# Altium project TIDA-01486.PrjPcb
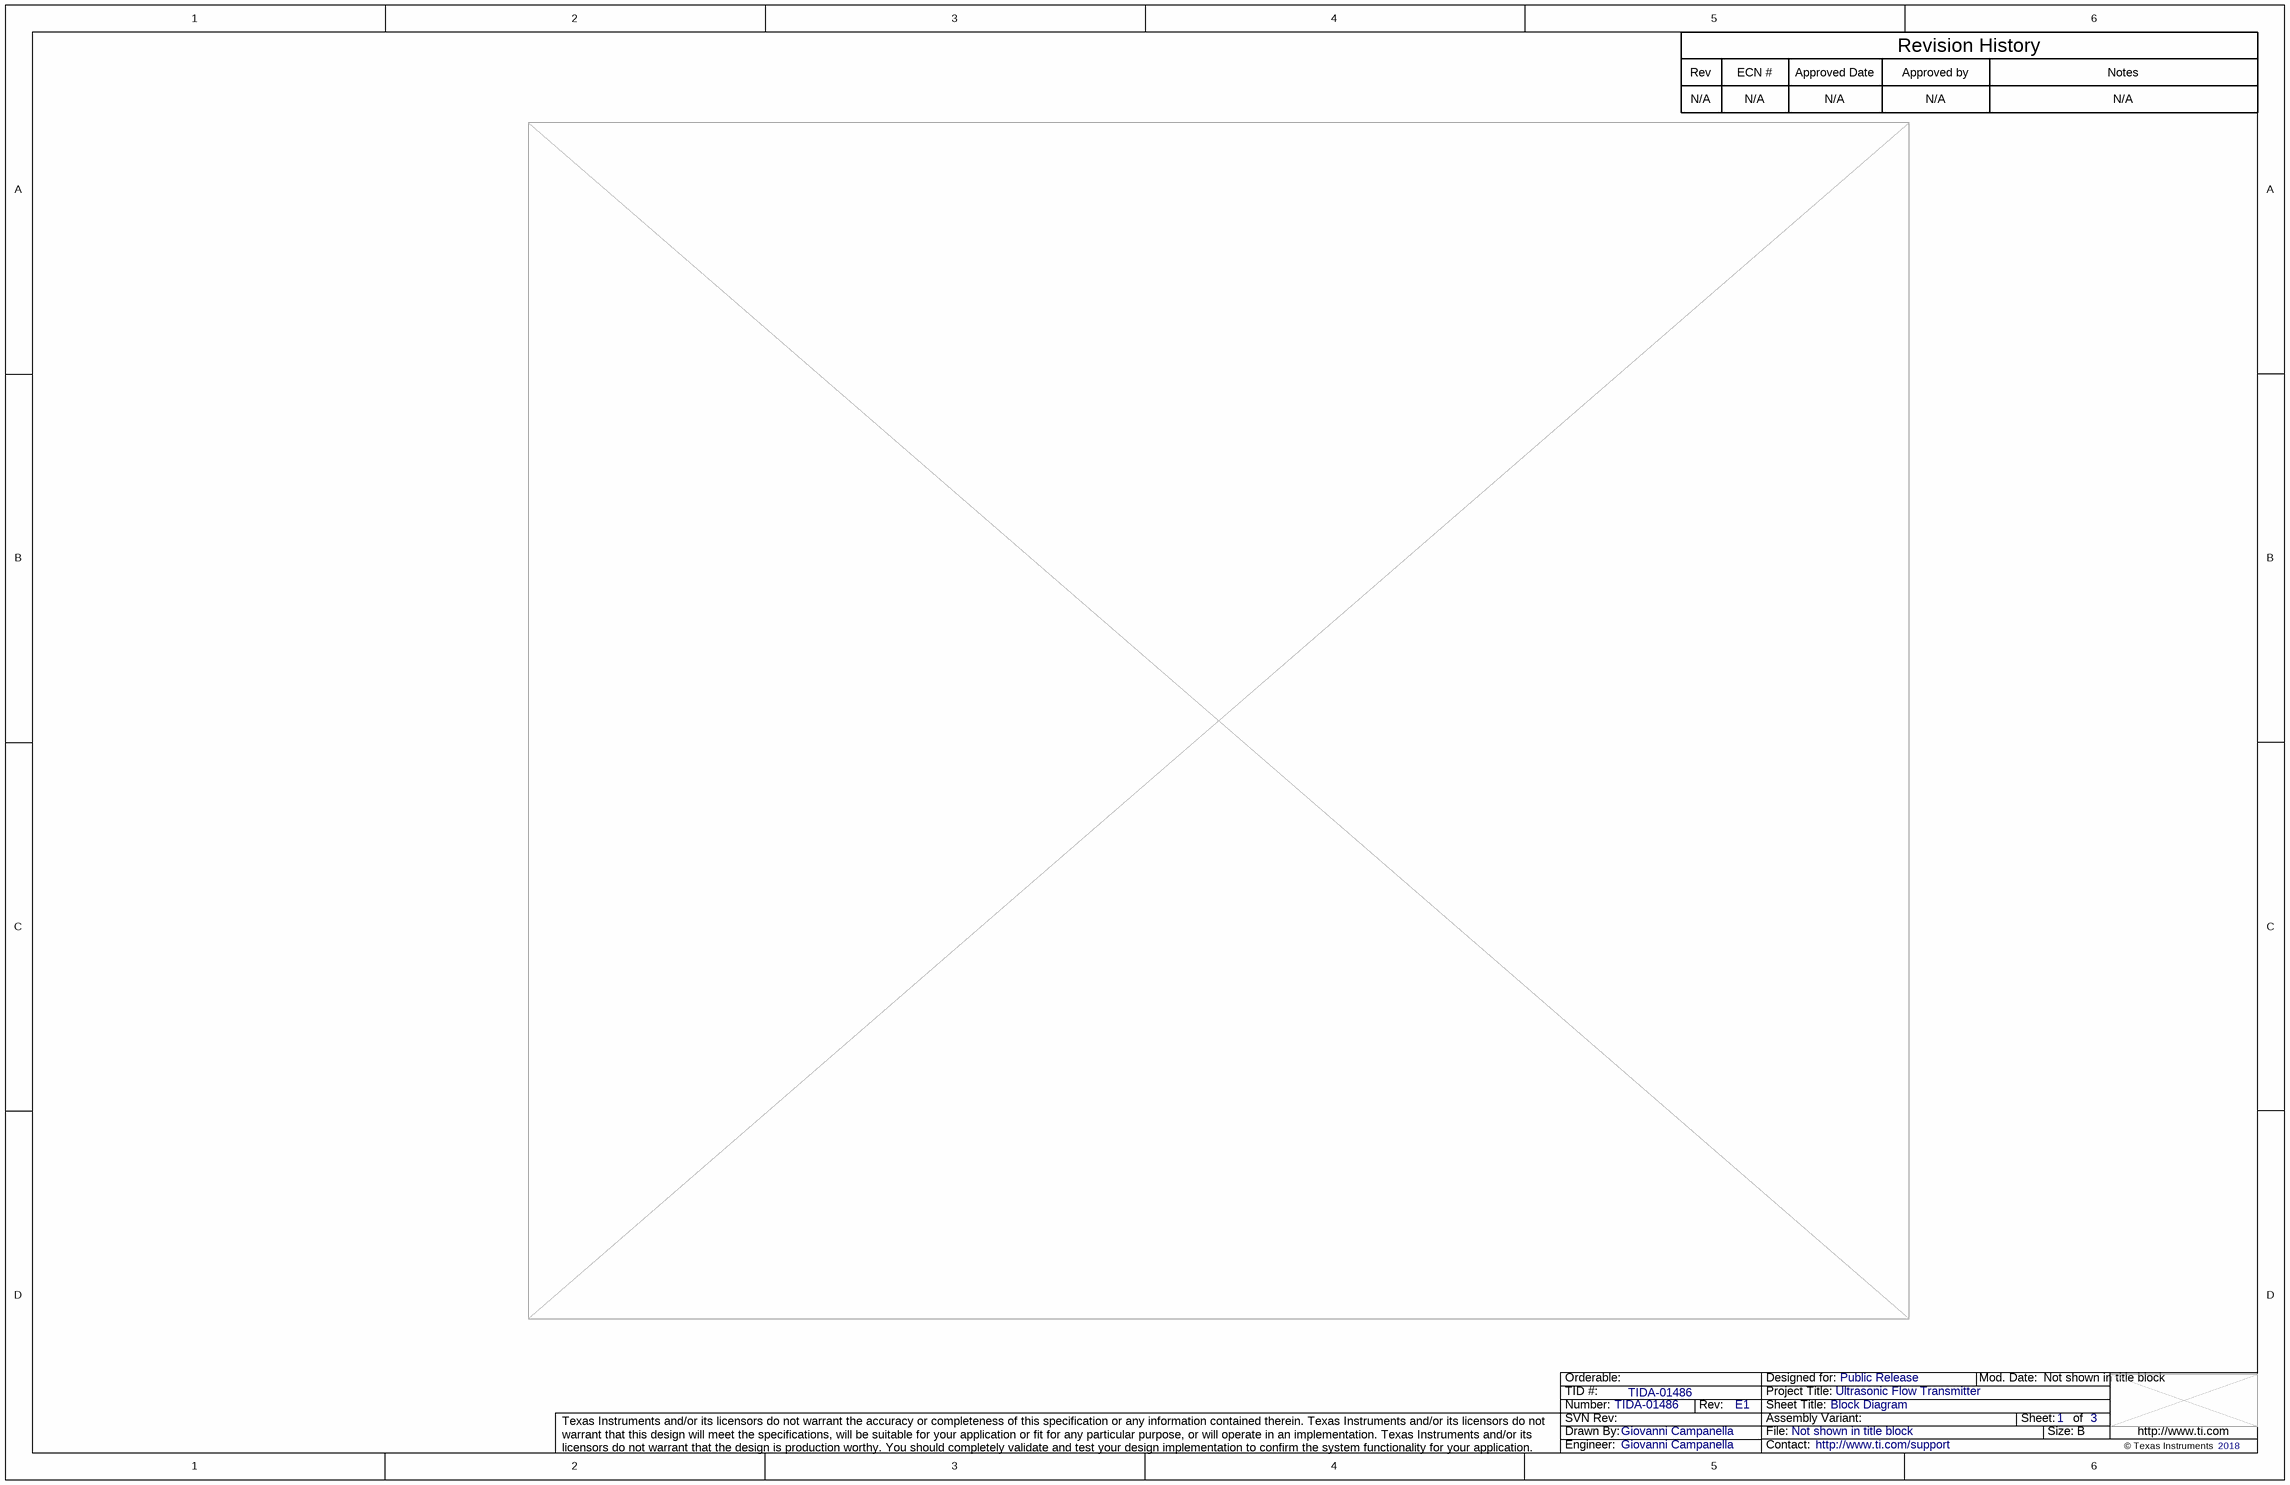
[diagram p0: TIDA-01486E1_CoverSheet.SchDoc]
TID: TIDA-01486; TechSupport: http://www.ti.com/support; SCH_Rev: E1; PRJ_Title: Ultrasonic Flow Transmitter; PRJ_Number: TIDA-01486; PRJ_Engineer: Giovanni Campanella; PRJ_Customer: Public Release; PCB_Rev: E1; PCB_Layout: Giovanni Campanella; CopyrightYear: 2018
3 sheets, 141 parts. Net scope: global (net labels, ports and power ports of the same name join across sheets).
Board file: TIDA-01486E1_PCB.PcbDoc
Sheets:
  TIDA-01486E1_CoverSheet.SchDoc
  TIDA-01486E1_Schematic.SchDoc
  TIDA-01486E1_Hardware.SchDoc

## Sheet TIDA-01486E1_CoverSheet.SchDoc: Block Diagram
size 431 x 279 mm; Date: Not shown in title block; ApprovedBy: Not shown in title block; CheckedBy: Not shown in title block; Author: Not shown in title block; CompanyName: Not shown in title block; DrawnBy: Giovanni Campanella; Engineer: Giovanni Campanella; Organization: Not shown in title block; Address1: Not shown in title block; Address2: Not shown in title block; Address3: Not shown in title block; Address4: Not shown in title block; DocumentNumber: 1; Revision: Use project parameter SCH_Rev; SheetNumber: 1; SheetTotal: 3; PageSetup: Record=PageOptions¦CenterHorizontal=True¦CenterVertical=True¦PrintScale=1.00¦XCorrection=1.00¦YCorrection=1.00¦PrintKind=0¦BorderSize=5000000¦LeftOffset=0¦BottomOffset=0¦Orientation=2¦PaperLength=1000¦PaperWidth=1000¦Scale=100¦PaperSource=15¦PrintQuality=600¦MediaType=1¦DitherType=10¦PaperKind=Letter¦PrintScaleMode=1

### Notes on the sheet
- Rev
- N/A
- ECN #
- Approved Date
- Approved by
- Revision History
- Notes

## Sheet TIDA-01486E1_Schematic.SchDoc: Schematic
size 431 x 279 mm; Date: Not shown in title block; ApprovedBy: Not shown in title block; CheckedBy: Not shown in title block; Author: Not shown in title block; CompanyName: Not shown in title block; DrawnBy: Giovanni Campanella; Engineer: Giovanni Campanella; Organization: Not shown in title block; Address1: Not shown in title block; Address2: Not shown in title block; Address3: Not shown in title block; Address4: Not shown in title block; DocumentNumber: 1; Revision: Use project parameter SCH_Rev; SheetNumber: 2; SheetTotal: 3; PageSetup: Record=PageOptions¦CenterHorizontal=True¦CenterVertical=True¦PrintScale=1.00¦XCorrection=1.00¦YCorrection=1.00¦PrintKind=0¦BorderSize=5000000¦LeftOffset=0¦BottomOffset=0¦Orientation=2¦PaperLength=1000¦PaperWidth=1000¦Scale=100¦PaperSource=15¦PrintQuality=600¦MediaType=1¦DitherType=10¦PaperKind=Letter¦PrintScaleMode=1
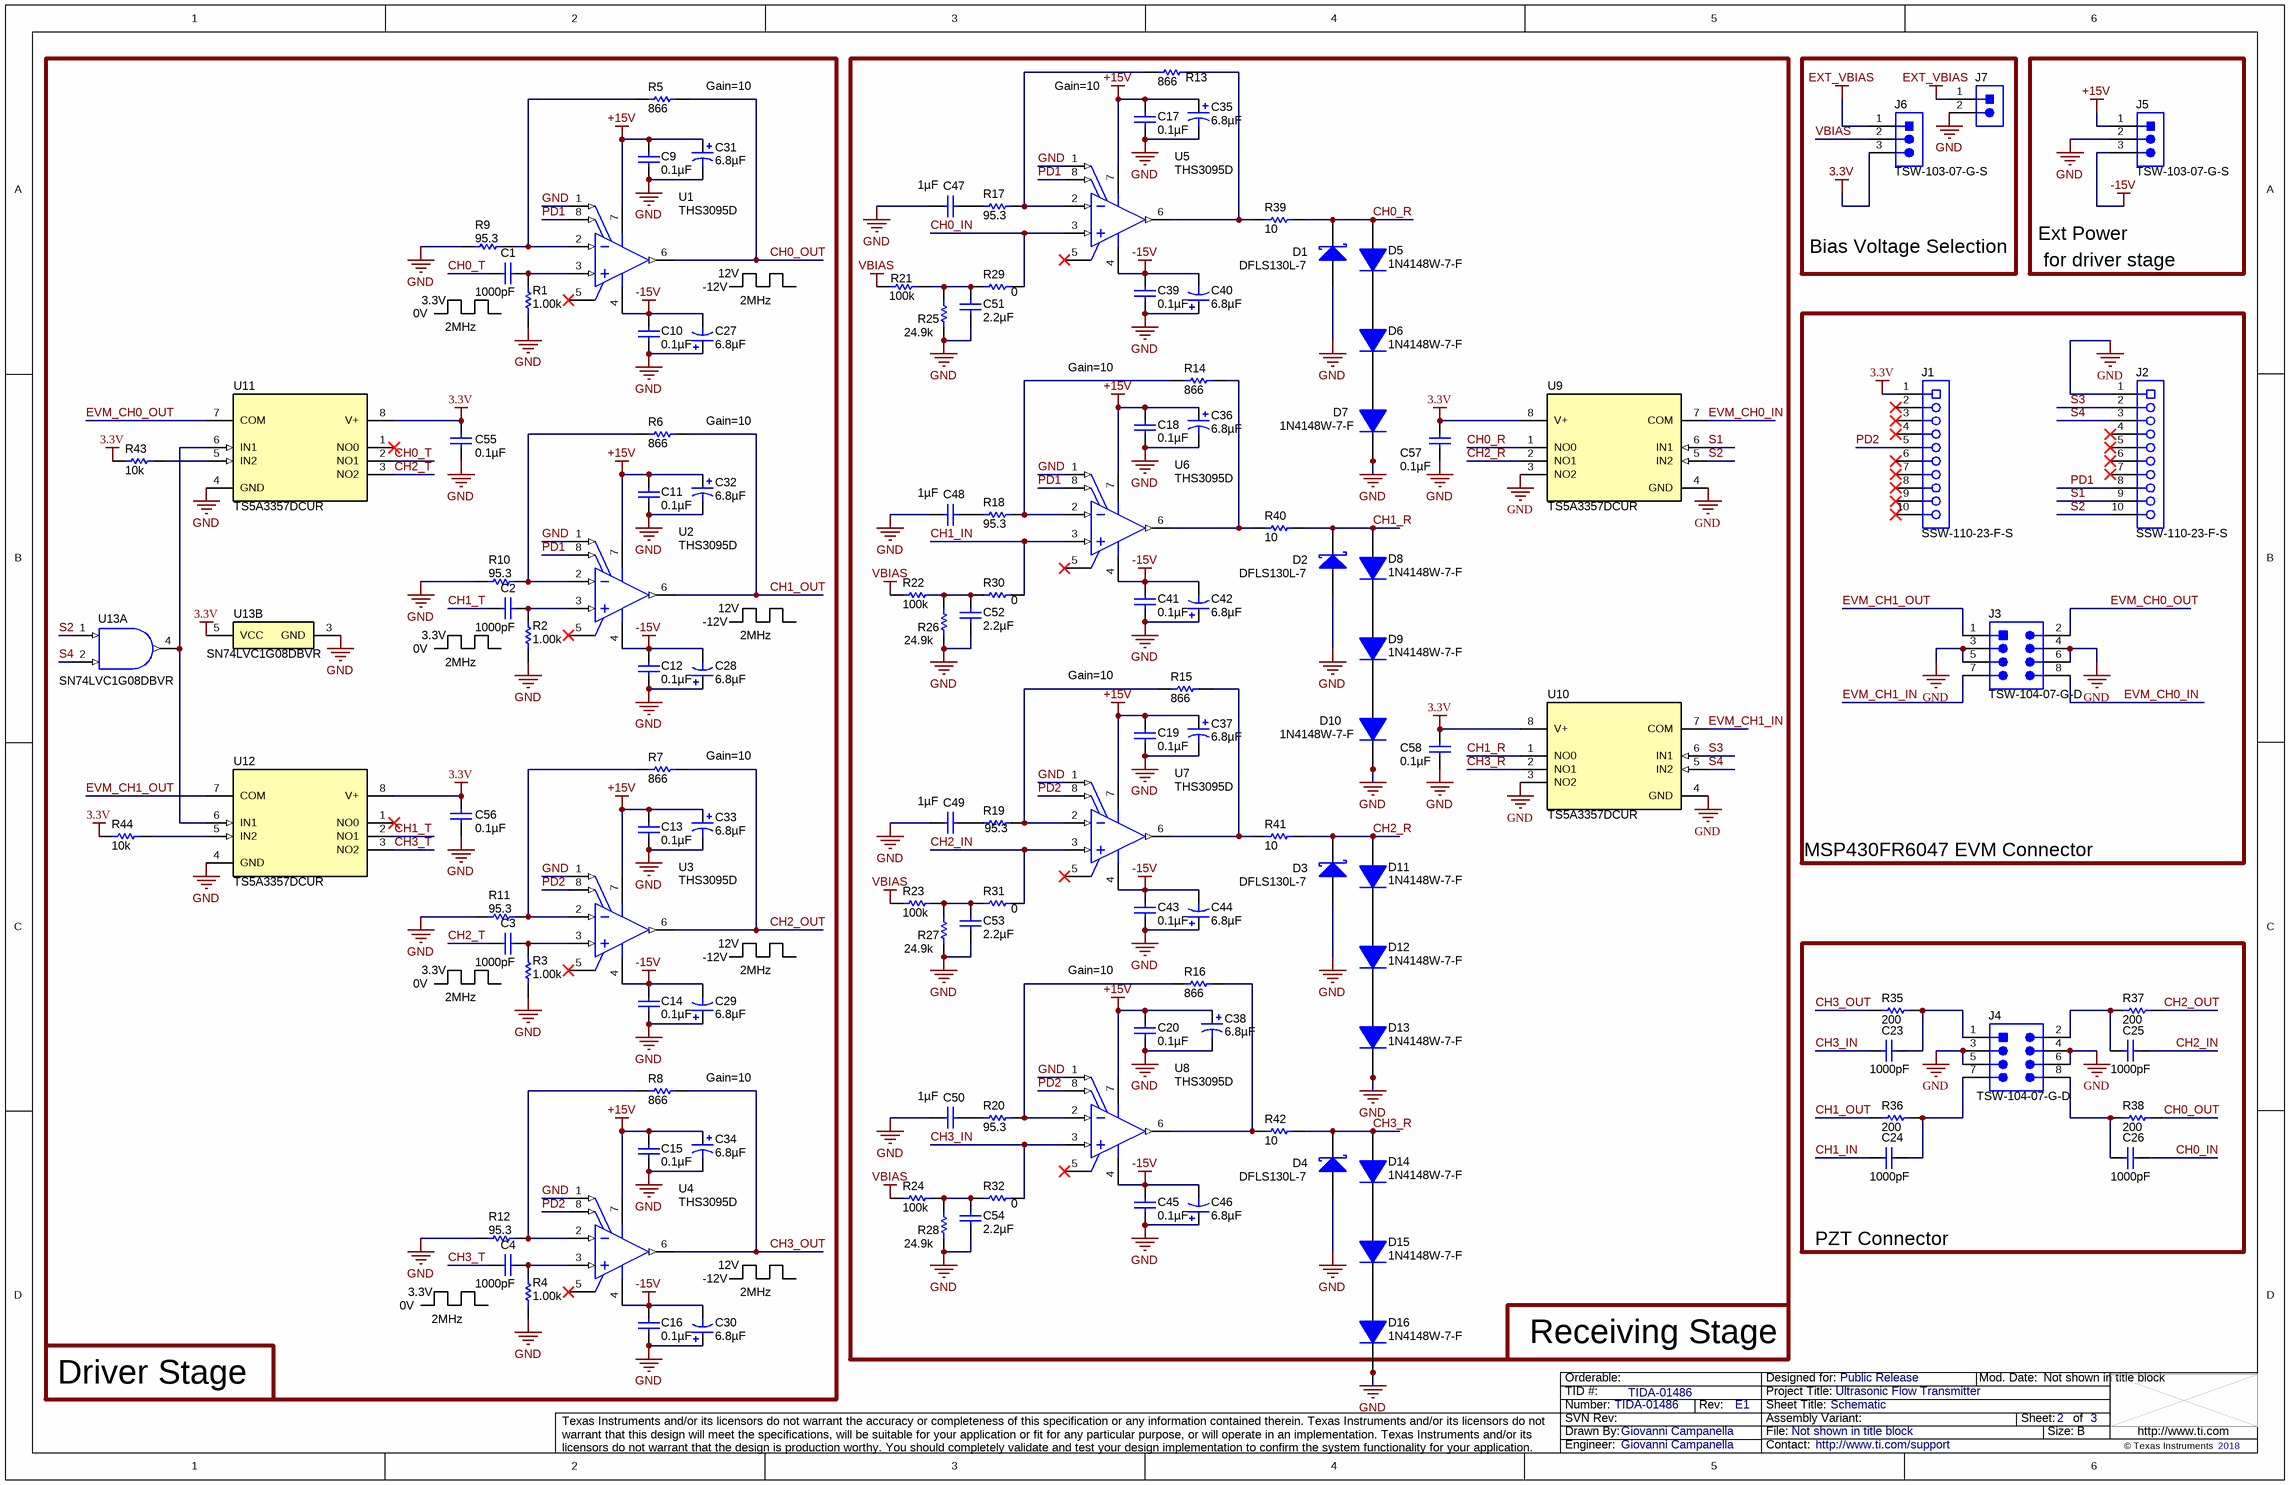
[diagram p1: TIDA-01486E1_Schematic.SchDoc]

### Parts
C1  ValueDisplayed: 1000pF  [0603]  (hidden comment: GRM188R71H102JA01D)
C2  ValueDisplayed: 1000pF  [0603]  (hidden comment: GRM188R71H102JA01D)
C3  ValueDisplayed: 1000pF  [0603]  (hidden comment: GRM188R71H102JA01D)
C4  ValueDisplayed: 1000pF  [0603]  (hidden comment: GRM188R71H102JA01D)
C9  ValueDisplayed: 0.1µF  [0402]  (hidden comment: GRM155R71E104KE14D)
C10  ValueDisplayed: 0.1µF  [0402]  (hidden comment: GRM155R71E104KE14D)
C11  ValueDisplayed: 0.1µF  [0402]  (hidden comment: GRM155R71E104KE14D)
C12  ValueDisplayed: 0.1µF  [0402]  (hidden comment: GRM155R71E104KE14D)
C13  ValueDisplayed: 0.1µF  [0402]  (hidden comment: GRM155R71E104KE14D)
C14  ValueDisplayed: 0.1µF  [0402]  (hidden comment: GRM155R71E104KE14D)
C15  ValueDisplayed: 0.1µF  [0402]  (hidden comment: GRM155R71E104KE14D)
C16  ValueDisplayed: 0.1µF  [0402]  (hidden comment: GRM155R71E104KE14D)
C17  ValueDisplayed: 0.1µF  [0402]  (hidden comment: GRM155R71E104KE14D)
C18  ValueDisplayed: 0.1µF  [0402]  (hidden comment: GRM155R71E104KE14D)
C19  ValueDisplayed: 0.1µF  [0402]  (hidden comment: GRM155R71E104KE14D)
C20  ValueDisplayed: 0.1µF  [0402]  (hidden comment: GRM155R71E104KE14D)
C23  ValueDisplayed: 1000pF  [0603]  (hidden comment: GRM1885C1H102FA01J)
C24  ValueDisplayed: 1000pF  [0603]  (hidden comment: GRM1885C1H102FA01J)
C25  ValueDisplayed: 1000pF  [0603]  (hidden comment: GRM1885C1H102FA01J)
C26  ValueDisplayed: 1000pF  [0603]  (hidden comment: GRM1885C1H102FA01J)
C27  ValueDisplayed: 6.8µF  [3216-18]  (hidden comment: TPSA685K020R1000)
C28  ValueDisplayed: 6.8µF  [3216-18]  (hidden comment: TPSA685K020R1000)
C29  ValueDisplayed: 6.8µF  [3216-18]  (hidden comment: TPSA685K020R1000)
C30  ValueDisplayed: 6.8µF  [3216-18]  (hidden comment: TPSA685K020R1000)
C31  ValueDisplayed: 6.8µF  [3216-18]  (hidden comment: TPSA685K020R1000)
C32  ValueDisplayed: 6.8µF  [3216-18]  (hidden comment: TPSA685K020R1000)
C33  ValueDisplayed: 6.8µF  [3216-18]  (hidden comment: TPSA685K020R1000)
C34  ValueDisplayed: 6.8µF  [3216-18]  (hidden comment: TPSA685K020R1000)
C35  ValueDisplayed: 6.8µF  [3216-18]  (hidden comment: TPSA685K020R1000)
C36  ValueDisplayed: 6.8µF  [3216-18]  (hidden comment: TPSA685K020R1000)
C37  ValueDisplayed: 6.8µF  [3216-18]  (hidden comment: TPSA685K020R1000)
C38  ValueDisplayed: 6.8µF  [3216-18]  (hidden comment: TPSA685K020R1000)
C39  ValueDisplayed: 0.1µF  [0402]  (hidden comment: GRM155R71E104KE14D)
C40  ValueDisplayed: 6.8µF  [3216-18]  (hidden comment: TPSA685K020R1000)
C41  ValueDisplayed: 0.1µF  [0402]  (hidden comment: GRM155R71E104KE14D)
C42  ValueDisplayed: 6.8µF  [3216-18]  (hidden comment: TPSA685K020R1000)
C43  ValueDisplayed: 0.1µF  [0402]  (hidden comment: GRM155R71E104KE14D)
C44  ValueDisplayed: 6.8µF  [3216-18]  (hidden comment: TPSA685K020R1000)
C45  ValueDisplayed: 0.1µF  [0402]  (hidden comment: GRM155R71E104KE14D)
C46  ValueDisplayed: 6.8µF  [3216-18]  (hidden comment: TPSA685K020R1000)
C47  ValueDisplayed: 1µF  [0603]  (hidden comment: GMK107AB7105KAHT)
C48  ValueDisplayed: 1µF  [0603]  (hidden comment: GMK107AB7105KAHT)
C49  ValueDisplayed: 1µF  [0603]  (hidden comment: GMK107AB7105KAHT)
C50  ValueDisplayed: 1µF  [0603]  (hidden comment: GMK107AB7105KAHT)
C51  ValueDisplayed: 2.2µF  [0603]  (hidden comment: EMK107BB7225MA-T)
C52  ValueDisplayed: 2.2µF  [0603]  (hidden comment: EMK107BB7225MA-T)
C53  ValueDisplayed: 2.2µF  [0603]  (hidden comment: EMK107BB7225MA-T)
C54  ValueDisplayed: 2.2µF  [0603]  (hidden comment: EMK107BB7225MA-T)
C55  ValueDisplayed: 0.1µF  [0402]  (hidden comment: GRM155R71E104KE14D)
C56  ValueDisplayed: 0.1µF  [0402]  (hidden comment: GRM155R71E104KE14D)
C57  ValueDisplayed: 0.1µF  [0402]  (hidden comment: GRM155R71E104KE14D)
C58  ValueDisplayed: 0.1µF  [0402]  (hidden comment: GRM155R71E104KE14D)
D1  DFLS130L-7  [PowerDI123]
D2  DFLS130L-7  [PowerDI123]
D3  DFLS130L-7  [PowerDI123]
D4  DFLS130L-7  [PowerDI123]
D5  1N4148W-7-F  [SOD-123]
D6  1N4148W-7-F  [SOD-123]
D7  1N4148W-7-F  [SOD-123]
D8  1N4148W-7-F  [SOD-123]
D9  1N4148W-7-F  [SOD-123]
D10  1N4148W-7-F  [SOD-123]
D11  1N4148W-7-F  [SOD-123]
D12  1N4148W-7-F  [SOD-123]
D13  1N4148W-7-F  [SOD-123]
D14  1N4148W-7-F  [SOD-123]
D15  1N4148W-7-F  [SOD-123]
D16  1N4148W-7-F  [SOD-123]
J1  SSW-110-23-F-S  [CONN_SSW-110-23-F-S]
J2  SSW-110-23-F-S  [CONN_SSW-110-23-F-S]
J3  TSW-104-07-G-D  [TSW-104-07-G-D]
J4  TSW-104-07-G-D  [TSW-104-07-G-D]
J5  TSW-103-07-G-S  [TSW-103-07-X-S]
J6  TSW-103-07-G-S  [TSW-103-07-X-S]
J7  TSW-102-07-G-S  [TSW-102-07-G-S]  (value not drawn)
R1  ValueDisplayed: 1.00k  [0603]  (hidden comment: RC0603FR-071KL)
R2  ValueDisplayed: 1.00k  [0603]  (hidden comment: RC0603FR-071KL)
R3  ValueDisplayed: 1.00k  [0603]  (hidden comment: RC0603FR-071KL)
R4  ValueDisplayed: 1.00k  [0603]  (hidden comment: RC0603FR-071KL)
R5  ValueDisplayed: 866  [0603]  (hidden comment: CRCW0603866RFKEA)
R6  ValueDisplayed: 866  [0603]  (hidden comment: CRCW0603866RFKEA)
R7  ValueDisplayed: 866  [0603]  (hidden comment: CRCW0603866RFKEA)
R8  ValueDisplayed: 866  [0603]  (hidden comment: CRCW0603866RFKEA)
R9  ValueDisplayed: 95.3  [0603]  (hidden comment: CRCW060395R3FKEA)
R10  ValueDisplayed: 95.3  [0603]  (hidden comment: CRCW060395R3FKEA)
R11  ValueDisplayed: 95.3  [0603]  (hidden comment: CRCW060395R3FKEA)
R12  ValueDisplayed: 95.3  [0603]  (hidden comment: CRCW060395R3FKEA)
R13  ValueDisplayed: 866  [0603]  (hidden comment: CRCW0603866RFKEA)
R14  ValueDisplayed: 866  [0603]  (hidden comment: CRCW0603866RFKEA)
R15  ValueDisplayed: 866  [0603]  (hidden comment: CRCW0603866RFKEA)
R16  ValueDisplayed: 866  [0603]  (hidden comment: CRCW0603866RFKEA)
R17  ValueDisplayed: 95.3  [0603]  (hidden comment: CRCW060395R3FKEA)
R18  ValueDisplayed: 95.3  [0603]  (hidden comment: CRCW060395R3FKEA)
R19  ValueDisplayed: 95.3  [0603]  (hidden comment: CRCW060395R3FKEA)
R20  ValueDisplayed: 95.3  [0603]  (hidden comment: CRCW060395R3FKEA)
R21  ValueDisplayed: 100k  [0603]  (hidden comment: RT0603BRD07100KL)
R22  ValueDisplayed: 100k  [0603]  (hidden comment: RT0603BRD07100KL)
R23  ValueDisplayed: 100k  [0603]  (hidden comment: RT0603BRD07100KL)
R24  ValueDisplayed: 100k  [0603]  (hidden comment: RT0603BRD07100KL)
R25  ValueDisplayed: 24.9k  [0603]  (hidden comment: RT0603BRD0724K9L)
R26  ValueDisplayed: 24.9k  [0603]  (hidden comment: RT0603BRD0724K9L)
R27  ValueDisplayed: 24.9k  [0603]  (hidden comment: RT0603BRD0724K9L)
R28  ValueDisplayed: 24.9k  [0603]  (hidden comment: RT0603BRD0724K9L)
R29  ValueDisplayed: 0  [0603]  (hidden comment: RMCF0603ZT0R00)
R30  ValueDisplayed: 0  [0603]  (hidden comment: RMCF0603ZT0R00)
R31  ValueDisplayed: 0  [0603]  (hidden comment: RMCF0603ZT0R00)
R32  ValueDisplayed: 0  [0603]  (hidden comment: RMCF0603ZT0R00)
R35  ValueDisplayed: 200  [0402]  (hidden comment: CRCW0402200RFKED)
R36  ValueDisplayed: 200  [0402]  (hidden comment: CRCW0402200RFKED)
R37  ValueDisplayed: 200  [0402]  (hidden comment: CRCW0402200RFKED)
R38  ValueDisplayed: 200  [0402]  (hidden comment: CRCW0402200RFKED)
R39  ValueDisplayed: 10  [0603]  (hidden comment: CRCW060310R0JNEAHP)
R40  ValueDisplayed: 10  [0603]  (hidden comment: CRCW060310R0JNEAHP)
R41  ValueDisplayed: 10  [0603]  (hidden comment: CRCW060310R0JNEAHP)
R42  ValueDisplayed: 10  [0603]  (hidden comment: CRCW060310R0JNEAHP)
R43  ValueDisplayed: 10k  [0402]  (hidden comment: CRCW040210K0JNED)
R44  ValueDisplayed: 10k  [0402]  (hidden comment: CRCW040210K0JNED)
U1  THS3095D  [D0008A_N]
U2  THS3095D  [D0008A_N]
U3  THS3095D  [D0008A_N]
U4  THS3095D  [D0008A_N]
U5  THS3095D  [D0008A_N]
U6  THS3095D  [D0008A_N]
U7  THS3095D  [D0008A_N]
U8  THS3095D  [D0008A_N]
U9  TS5A3357DCUR  [DCU0008A_N]
U10  TS5A3357DCUR  [DCU0008A_N]
U11  TS5A3357DCUR  [DCU0008A_N]
U12  TS5A3357DCUR  [DCU0008A_N]
U13  SN74LVC1G08DBVR  [DBV0005A_N]  (parts A,B of 2)

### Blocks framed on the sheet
Driver Stage: C1-C4 C9-C16 C27-C34 C55 C56 R1-R12 R43 R44 U1-U4 U11-U13
Receiving Stage: C17-C20 C35-C54 C57 C58 D1-D16 R13-R32 R39-R42 U5-U10
Bias Voltage Selection: J6 J7
MSP430FR6047 EVM Connector: J1-J3
PZT Connector: C23-C26 J4 R35-R38

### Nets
3.3V: C55.1 C56.1 C57.1 C58.1 J1.1 J6.3 R43.1 R44.1 U9.8(V+) U10.8(V+) U11.8(V+) U12.8(V+) U13.5(VCC)
+15V: C9.1 C11.1 C13.1 C15.1 C17.1 C18.1 C19.1 C20.1 C31.1(+) C32.1(+) C33.1(+) C34.1(+) C35.1(+) C36.1(+) C37.1(+) C38.1(+) J5.1 U1.7(VS+) U2.7(VS+) U3.7(VS+) U4.7(VS+) U5.7(VS+) U6.7(VS+) U7.7(VS+) U8.7(VS+)
-15V: C10.1 C12.1 C14.1 C16.1 C27.2(-) C28.2(-) C29.2(-) C30.2(-) C39.1 C40.2(-) C41.1 C42.2(-) C43.1 C44.2(-) C45.1 C46.2(-) J5.3 U1.4(VS-) U2.4(VS-) U3.4(VS-) U4.4(VS-) U5.4(VS-) U6.4(VS-) U7.4(VS-) U8.4(VS-)
EXT_VBIAS: J6.1 J7.1
GND: C9.2 C10.2 C11.2 C12.2 C13.2 C14.2 C15.2 C16.2 C17.2 C18.2 C19.2 C20.2 C27.1(+) C28.1(+) C29.1(+) C30.1(+) C31.2(-) C32.2(-) C33.2(-) C34.2(-) C35.2(-) C36.2(-) C37.2(-) C38.2(-) C39.2 C40.1(+) C41.2 C42.1(+) C43.2 C44.1(+) C45.2 C46.1(+) C47.2 C48.2 C49.2 C50.2 C51.2 C52.2 C53.2 C54.2 C55.2 C56.2 C57.2 C58.2 D1.2(A) D2.2(A) D3.2(A) D4.2(A) D7.1(K) D10.1(K) D13.1(K) D16.1(K) J2.1 J3.3 J3.4 J3.5 J3.6 J4.3 J4.4 J4.5 J4.6 J5.2 J7.2 R1.1 R2.1 R3.1 R4.1 R9.1 R10.1 R11.1 R12.1 R25.1 R26.1 R27.1 R28.1 U1.1(REF) U2.1(REF) U3.1(REF) U4.1(REF) U5.1(REF) U6.1(REF) U7.1(REF) U8.1(REF) U9.3(NO2) U9.4(GND) U10.3(NO2) U10.4(GND) U11.4(GND) U12.4(GND) U13.3(GND)
VBIAS: J6.2 R21.1 R22.1 R23.1 R24.1
CH0_IN: C26.1 R29.2 U5.3(VIN+)
CH0_OUT: R5.2 R38.2 U1.6(VOUT)
CH0_R: D1.1(K) D5.2(A) R39.2 U9.1(NO0)
CH0_T: C1.2 U11.2(NO1)
CH1_IN: C24.2 R30.2 U6.3(VIN+)
CH1_OUT: R6.2 R36.1 U2.6(VOUT)
CH1_R: D2.1(K) D8.2(A) R40.2 U10.1(NO0)
CH1_T: C2.2 U12.2(NO1)
CH2_IN: C25.1 R31.2 U7.3(VIN+)
CH2_OUT: R7.2 R37.2 U3.6(VOUT)
CH2_R: D3.1(K) D11.2(A) R41.2 U9.2(NO1)
CH2_T: C3.2 U11.3(NO2)
CH3_IN: C23.2 R32.2 U8.3(VIN+)
CH3_OUT: R8.2 R35.1 U4.6(VOUT)
CH3_R: D4.1(K) D14.2(A) R42.2 U10.2(NO1)
CH3_T: C4.2 U12.3(NO2)
EVM_CH0_IN: J3.8 U9.7(COM)
EVM_CH0_OUT: J3.2 U11.7(COM)
EVM_CH1_IN: J3.7 U10.7(COM)
EVM_CH1_OUT: J3.1 U12.7(COM)
PD1: J2.8 U1.8(~{PD}) U2.8(~{PD}) U5.8(~{PD}) U6.8(~{PD})
PD2: J1.5 U3.8(~{PD}) U4.8(~{PD}) U7.8(~{PD}) U8.8(~{PD})
S1: J2.9 U9.6(IN1)
S2: J2.10 U9.5(IN2) U13.1(A)
S3: J2.2 U10.6(IN1)
S4: J2.3 U10.5(IN2) U13.2(B)
NetC1_1: C1.1 R1.2 U1.3(VIN+)
NetC2_1: C2.1 R2.2 U2.3(VIN+)
NetC3_1: C3.1 R3.2 U3.3(VIN+)
NetC4_1: C4.1 R4.2 U4.3(VIN+)
NetC23_1: C23.1 J4.1 R35.2
NetC24_1: C24.1 J4.7 R36.2
NetC25_2: C25.2 J4.2 R37.1
NetC26_2: C26.2 J4.8 R38.1
NetC47_1: C47.1 R17.1
NetC48_1: C48.1 R18.1
NetC49_1: C49.1 R19.1
NetC50_1: C50.1 R20.1
NetC51_1: C51.1 R21.2 R25.2 R29.1
NetC52_1: C52.1 R22.2 R26.2 R30.1
NetC53_1: C53.1 R23.2 R27.2 R31.1
NetC54_1: C54.1 R24.2 R28.2 R32.1
NetD5_1: D5.1(K) D6.2(A)
NetD6_1: D6.1(K) D7.2(A)
NetD8_1: D8.1(K) D9.2(A)
NetD9_1: D9.1(K) D10.2(A)
NetD11_1: D11.1(K) D12.2(A)
NetD12_1: D12.1(K) D13.2(A)
NetD14_1: D14.1(K) D15.2(A)
NetD15_1: D15.1(K) D16.2(A)
NetR5_1: R5.1 R9.2 U1.2(VIN-)
NetR6_1: R6.1 R10.2 U2.2(VIN-)
NetR7_1: R7.1 R11.2 U3.2(VIN-)
NetR8_1: R8.1 R12.2 U4.2(VIN-)
NetR13_1: R13.1 R17.2 U5.2(VIN-)
NetR13_2: R13.2 R39.1 U5.6(VOUT)
NetR14_1: R14.1 R18.2 U6.2(VIN-)
NetR14_2: R14.2 R40.1 U6.6(VOUT)
NetR15_1: R15.1 R19.2 U7.2(VIN-)
NetR15_2: R15.2 R41.1 U7.6(VOUT)
NetR16_1: R16.1 R20.2 U8.2(VIN-)
NetR16_2: R16.2 R42.1 U8.6(VOUT)
NetR43_2: R43.2 U11.5(IN2)
NetR44_2: R44.2 U12.5(IN2)
NetU11_6: U11.6(IN1) U12.6(IN1) U13.4(Y)

Not connected (* = marked no-connect by the designer): J1 2* 3* 4* 6* 7* 8* 9* 10*; J2 4* 5* 6* 7*; U1 5(NC)*; U2 5(NC)*; U3 5(NC)*; U4 5(NC)*; U5 5(NC)*; U6 5(NC)*; U7 5(NC)*; U8 5(NC)*; U11 1(NO0)*; U12 1(NO0)*

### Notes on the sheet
- (near R5) Gain=10
- Gain=10
- Ext Power
- 3.3V
- (near C27) -12V
- 12V
- (near C27) 2MHz
- for driver stage
- 0V
- 2MHz
- (near R6) Gain=10
- (near C28) -12V
- (near C28) 2MHz
- (near R7) Gain=10
- (near C29) -12V
- (near C29) 2MHz
- (near R8) Gain=10
- (near C30) -12V
- (near C30) 2MHz

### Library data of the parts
C1-C4 = GRM188R71H102JA01D: CAP, CERM, 1000 pF, 50 V,+/- 5%, X7R, 0603; Manufacturer: MuRata; Polarized: N; CompType: Capacitor; Value: 1000pF; U/M: EA; Cap_F: 0.000000001; Tolerance_%: 5; Value1: Unknown; VDC_V: 50; Value2: 50V; TaMin_C: -55; TaMax_C: 125; SizeArea_mm2: 1.28; SizeAreaWB_mm2: 4.68; SizeX_mm: 1.6; SizeY_mm: 0.8; SizeZ_mm: 1; AEC Category: Q200
C9-C20 C39 C41 C43 C45 C55-C58 = GRM155R71E104KE14D: CAP, CERM, 0.1 µF, 25 V,+/- 10%, X7R, 0402; Manufacturer: MuRata; Polarized: N; CompType: Capacitor; Value: 0.1uF; U/M: EA; Cap_F: 0.0000001; Tolerance_%: 10; Value1: Unknown; VDC_V: 25; Value2: 25V; TaMin_C: -55; TaMax_C: 125; SizeArea_mm2: 0.5; SizeAreaWB_mm2: 3; SizeX_mm: 1; SizeZ_mm: 0.6; AEC Category: Q200; Green_Lifecycle: Active; Green_REACh: Passed
C23-C26 = GRM1885C1H102FA01J: CAP, CERM, 1000 pF, 50 V,+/- 1%, C0G/NP0, 0603; Manufacturer: MuRata; Polarized: N; CompType: Capacitor; Value: 1000pF; U/M: EA; Cap_F: 0.000000001; Tolerance_%: 1; Value1: Unknown; VDC_V: 50; Value2: 50V; TaMin_C: -55; TaMax_C: 125; SizeArea_mm2: 1.28; SizeAreaWB_mm2: 4.68; SizeX_mm: 1.6; SizeY_mm: 0.8; AEC Category: Q200; Green_Lifecycle: Not Set; Green_REACh: Incomplete
C27-C38 C40 C42 C44 C46 = TPSA685K020R1000: CAP, TA, 6.8 µF, 20 V, +/- 10%, 1 ohm, SMD; Manufacturer: AVX; Polarized: Y; CompType: Capacitor; Value: 6.8uF; U/M: EA; Cap_F: 0.0000068; Tolerance_%: 10; Value1: 1 ohm; VDC_V: 20; Value2: 20V; ESR_ohm: 1; IRMS_A: 0.246; TaMin_C: -55; TaMax_C: 125; Cap_Case: A; SizeAreaWB_mm2: 10.92; SizeArea_mm2: 5.12; SizeX_mm: 3.2; SizeY_mm: 1.6; SizeZ_mm: 1.8; AEC Category: Q200
C47-C50 = GMK107AB7105KAHT: CAP, CERM, 1 µF, 35 V,+/- 10%, X7R, AEC-Q200 Grade 0, 0603; Manufacturer: Taiyo Yuden; Polarized: N; CompType: Capacitor; Value: 1uF; U/M: EA; Cap_F: 0.000001; Tolerance_%: 10; Value1: Unknown; VDC_V: 35; Value2: 35V; TaMin_C: -55; TaMax_C: 125; SizeArea_mm2: 1.28; SizeAreaWB_mm2: 4.68; SizeX_mm: 1.6; SizeY_mm: 0.8; SizeZ_mm: 1; AEC Category: Q200; AEC Qualified: Y; AEC Grade: 0
C51-C54 = EMK107BB7225MA-T: CAP, CERM, 2.2 µF, 16 V,+/- 10%, X7R, 0603; Manufacturer: Taiyo Yuden; Polarized: N; CompType: Capacitor; Value: 2.2uF; U/M: EA; Cap_F: 0.0000022; Tolerance_%: 10; Value1: Unknown; VDC_V: 16; Value2: 16V; TaMin_C: -55; TaMax_C: 125; SizeArea_mm2: 1.28; SizeAreaWB_mm2: 4.68; SizeX_mm: 1.6; SizeY_mm: 0.8; SizeZ_mm: 1; AEC Category: Q200
D1-D4 = DFLS130L-7: Diode, Schottky, 30 V, 1 A, PowerDI123; Manufacturer: Diodes Inc.; U/M: EA; Vf_V: 0.31; Value: 30V; Value1: 1A; Value2: 0.31V; Io_A: 1; Vr_V: 30; TJmax_C: 125; SizeAreaWB_mm2: 13.066; SizeArea_mm2: 6.586; SizeX_mm: 3.7; SizeY_mm: 1.78; SizeZ_mm: 0.98; AEC Category: Q101; AEC Qualified: N; Green_Lifecycle: Not Set; Green_REACh: Incomplete
D5-D16 = CMP-0029001-1: Diode, Ultrafast, 100 V, 0.15 A, SOD-123; Manufacturer: Diodes Inc.; Io_A: 1.5dA; Green_Lifecycle: Active; SizeAreaWB_mm2: 13.095; Vr_V: 100V; Green_REACh: Passed; Value1: 0.15A; TJmax_C: 150°C; U/M: EA; Value: 100V; SizeZ_mm: 1.35; SizeX_mm: 3.85; SizeY_mm: 1.7; Vf_V: 1.25V; SizeArea_mm2: 6.545; AEC Category: Q101
J1 J2 = CMP-0075441-1: Connector, Receptacle, 100mil, 10x1, Gold plated, TH; Manufacturer: Samtec; Green_Lifecycle: Active; CompType: Socket Strip; Green_REACh: Passed; CT: True; CNHeader: False
J3 J4 = CMP-0075408-1: Header, 100mil, 4x2, Gold, TH; Manufacturer: Samtec; Pitch_mm: 2.54; Cert_VDE: N; Gender: Male; Cert_CSA: Y; Voltage_V: 550V; Green_REACh: Passed; Current_A: 6.3A; CT: False; Green_Lifecycle: Active; Row_Count: 2; CNHeader: True
J5 J6 = CMP-0075407-1: Header, 100mil, 3x1, Gold, TH; Manufacturer: Samtec; Pitch_mm: 2.54; Cert_VDE: N; Gender: Male; Cert_CSA: Y; Voltage_V: 550V; Green_REACh: Passed; Current_A: 6.3A; CT: False; Green_Lifecycle: Active; Row_Count: 1; CNHeader: True
J7 = CMP-0075405-2: Header, 100mil, 2x1, Gold, TH; Manufacturer: Samtec; Pitch_mm: 2.54; Cert_VDE: N; Gender: Male; Cert_CSA: Y; Voltage_V: 550V; Green_REACh: Passed; Current_A: 6.3A; Green_Lifecycle: Active; Row_Count: 1
R1-R4 = RC0603FR-071KL: RES, 1.00 k, 1%, 0.1 W, 0603; Manufacturer: Yageo America; CompType: Resistor; Value: 1.00k; Res_ohm: 1000; Value_Code: 1k00; Tolerance_%: 1; Power_W: 0.1; Value2: 0.1W; VDC_V: 150; TempCo: 200 ppm/C; SizeArea_mm2: 1.28; SizeX_mm: 1.6; SizeY_mm: 0.8; EIA_Code: E96; U/M: EA; AEC Category: Q200; Green_Lifecycle: Active; Green_REACh: Passed
R5-R8 R13-R16 = CRCW0603866RFKEA: RES, 866, 1%, 0.1 W, 0603; Manufacturer: Vishay-Dale; CompType: Resistor; Value: 866; Value_Code: 866R; Tolerance_%: 1; Power_W: 0.1; Value2: 0.1W; VDC_V: 75; TempCo: 100 ppm/C; SizeArea_mm2: 1.28; SizeX_mm: 1.6; SizeY_mm: 0.8; EIA_Code: E96; U/M: EA; AEC Category: Q200; Green_Lifecycle: Active; Green_REACh: Passed
R9-R12 R17-R20 = CRCW060395R3FKEA: RES, 95.3, 1%, 0.1 W, 0603; Manufacturer: Vishay-Dale; CompType: Resistor; Value: 95.3; Value_Code: 95R3; Tolerance_%: 1; Power_W: 0.1; Value2: 0.1W; VDC_V: 75; TempCo: 100 ppm/C; SizeArea_mm2: 1.28; SizeX_mm: 1.6; SizeY_mm: 0.8; EIA_Code: E96; U/M: EA; AEC Category: Q200
R21-R24 = RT0603BRD07100KL: RES, 100 k, 0.1%, 0.1 W, 0603; Manufacturer: Yageo America; CompType: Resistor; Value: 100k; Res_ohm: 100000; Tolerance_%: 0.1; Value2: 0.1W; VDC_V: 75; TempCo: 25 ppm/C; SizeArea_mm2: 1.28; SizeX_mm: 1.6; SizeY_mm: 0.8; SizeZ_mm: 1; EIA_Code: E192; U/M: EA; AEC Category: Q200; Green_Lifecycle: Active; Green_REACh: Passed
R25-R28 = RT0603BRD0724K9L: RES, 24.9 k, 0.1%, 0.1 W, 0603; Manufacturer: Yageo America; CompType: Resistor; Value: 24.9k; Res_ohm: 24900; Value_Code: 24k9; Tolerance_%: 0.1; Value2: 0.1W; VDC_V: 75; TempCo: 25 ppm/C; SizeArea_mm2: 1.28; SizeX_mm: 1.6; SizeY_mm: 0.8; SizeZ_mm: 1; EIA_Code: E192; U/M: EA; AEC Category: Q200
R29-R32 = RMCF0603ZT0R00: RES, 0, 1%, 0.1 W, AEC-Q200 Grade 0, 0603; Manufacturer: Stackpole Electronics Inc; CompType: Resistor; Value: 0; Tolerance_%: 1; Power_W: 0.1; Value2: 0.1W; TempCo: ppm/C; SizeArea_mm2: 1.28; SizeX_mm: 1.6; SizeY_mm: 0.8; U/M: EA; AEC Category: Q200; AEC Qualified: Y; Green_Lifecycle: Active; Green_REACh: Passed
R35-R38 = CRCW0402200RFKED: RES, 200, 1%, 0.063 W, 0402; Manufacturer: Vishay-Dale; CompType: Resistor; Value: 200; Value_Code: 200R; Tolerance_%: 1; Power_W: 0.063; Value2: 0.063W; VDC_V: 50; TempCo: 100 ppm/C; SizeArea_mm2: 0.5; SizeZ_mm: 0.6; EIA_Code: E96; U/M: EA; AEC Category: Q200; Green_Lifecycle: Active; Green_REACh: Passed
R39-R42 = CRCW060310R0JNEAHP: RES, 10, 5%, 0.25 W, 0603; Manufacturer: Vishay-Dale; CompType: Resistor; Value: 10; Value_Code: 10R0; Tolerance_%: 5; Power_W: 0.25; Value2: 0.25W; VDC_V: 75; TempCo: 200 ppm/C; SizeArea_mm2: 1.28; SizeX_mm: 1.6; SizeY_mm: 0.8; SizeZ_mm: 1; EIA_Code: E24; U/M: EA; AEC Category: Q200; Green_Lifecycle: Active; Green_REACh: Passed
R43 R44 = CRCW040210K0JNED: RES, 10 k, 5%, 0.063 W, 0402; Manufacturer: Vishay-Dale; CompType: Resistor; Value: 10k; Res_ohm: 10000; Value_Code: 10k0; Tolerance_%: 5; Power_W: 0.063; Value2: 0.063W; VDC_V: 50; TempCo: 200 ppm/C; SizeArea_mm2: 0.5; SizeX_mm: 1; SizeZ_mm: 0.6; EIA_Code: E24; U/M: EA; AEC Category: Q200; Green_Lifecycle: Active; Green_REACh: Passed
U1-U8 = THS3095D: Single-High-Voltage, Low Distortion, Current-Feedback Operational Amplifier with Power-Down, 10 to 30 V, -40 to 85 degC, 8-pin SOIC (D8), Green (RoHS & no Sb/Br); Alternate Manufacturer: Texas Instruments; Alternate PartNumber: Equivalent; 2nd Harmonic(dBc): 66; 3rd Harmonic(dBc): 74; @ MHz: 10; Acl, min stable gain(V/V): 1; BW @ Acl(MHz): 210; Diff Gain(%): 0.013; Diff Phase(deg): 0.02; Iib(Max)(nA): 20000; Io(Typ)(mA): 250; Iq per channel(Max)(mA): 11; Settling Time (0.1%)(Typ)(ns): 42; Slew Rate(Typ)(V/us): 7300; Sub Family: High Output Current Amplifier (>=50mA), High Speed Amplifier (>=50MHz), High Supply Voltage Amplifier (>=30V); THD (Fc is 1 MHz)(Typ)(dB): -75; Vio(Max)(mV): 4; Vn at Flatband(Typ)(nV/rtHz): 2; Vs(Max)(V): 30
U9-U12 = TS5A3357DCUR: Single 5-Ohm SP3T Analog Switch 5-V/3.3-V 3:1 Analog Multiplexer/Demultiplexer, DCU0008A (VSSOP-8); Alternate PartNumber: TS5A3357DCUT; Manufacturer: Texas Instruments; SymbolCreator: Altium; SizeArea_mm2: 6.4; SizeAreaWB_mm2: 12.6; SizeX_mm: 3.2; SizeY_mm: 2; SizeZ_mm: 0.9; CompType: IC; U/M: EA
U13 = SN74LVC1G08DBVR: Single 2-Input Positive-AND Gate, DBV0005A, LARGE T&R; Manufacturer: Texas Instruments; Alternate PartNumber: Equivalent; VCC(Min)(V): 1.65; VCC(Max)(V): 5.5; Output Type: CMOS; ICC @ Nom Voltage(Max)(mA): 0.01; Input Type: CMOS/TTL; Bits(#): 1; F @ Nom Voltage(Max)(Mhz): 150; Rating: Catalog; Technology Family: LVC; Voltage(Nom)(V): 1.8,2.5,3.3,5; Schmitt Trigger: No; Output Drive (IOL/IOH)(Max)(mA): 32/-32; tpd @ Nom Voltage(Max)(ns): 4.5,6,4,5; Logic: True; Gate Type: AND

## Sheet TIDA-01486E1_Hardware.SchDoc: Hardware
size 431 x 279 mm; Date: Not shown in title block; ApprovedBy: Not shown in title block; CheckedBy: Not shown in title block; Author: Not shown in title block; CompanyName: Not shown in title block; DrawnBy: Giovanni Campanella; Engineer: Giovanni Campanella; Organization: Not shown in title block; Address1: Not shown in title block; Address2: Not shown in title block; Address3: Not shown in title block; Address4: Not shown in title block; DocumentNumber: 1; Revision: Use project parameter SCH_Rev; SheetNumber: 3; SheetTotal: 3; PageSetup: Record=PageOptions¦CenterHorizontal=True¦CenterVertical=True¦PrintScale=1.00¦XCorrection=1.00¦YCorrection=1.00¦PrintKind=0¦BorderSize=5000000¦LeftOffset=0¦BottomOffset=0¦Orientation=2¦PaperLength=1000¦PaperWidth=1000¦Scale=100¦PaperSource=15¦PrintQuality=600¦MediaType=1¦DitherType=10¦PaperKind=Letter¦PrintScaleMode=1
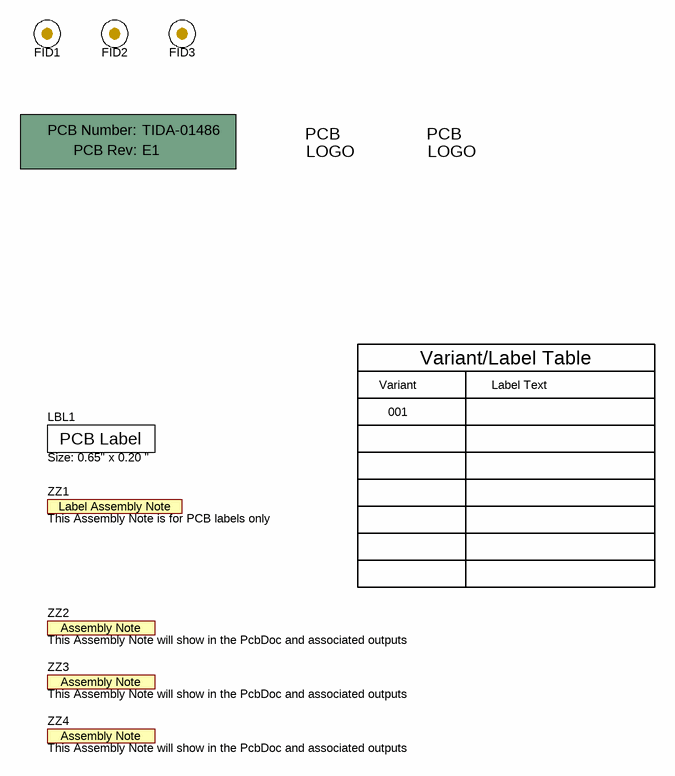
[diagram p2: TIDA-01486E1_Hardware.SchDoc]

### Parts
!PCB  Printed Circuit Board  (value not drawn)  (mechanical)
FID1  Fiducial  [Fiducial10-20]  (value not drawn)
FID2  Fiducial  [Fiducial10-20]  (value not drawn)
FID3  Fiducial  [Fiducial10-20]  (value not drawn)
LBL1  Size: 0.65" x 0.20 "  [Label_650x200]
Logo2  Pb-Free Symbol  [Pb-Free_Overlay_Small]  (value not drawn)  (no BOM)
Logo3  FCC disclaimer  [FCC_disclaimer]  (value not drawn)  (no BOM)
ZZ1  This Assembly Note is for PCB labels only  [AssemblyNoteLabel]  (no BOM)
ZZ2  This Assembly Note will show in the PcbDoc and associated outputs  [AssemblyNote]  (no BOM)
ZZ3  This Assembly Note will show in the PcbDoc and associated outputs  [AssemblyNote]  (no BOM)
ZZ4  This Assembly Note will show in the PcbDoc and associated outputs  [AssemblyNote]  (no BOM)

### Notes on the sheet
- Variant/Label Table
- Variant
- 001
- Label Text

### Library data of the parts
!PCB = PCB: Manufacturer: Any; PartNumber: TIDA-01486; SymbolCreator: a0412235
FID1-FID3 = Fiducial: Fiducial mark.  There is nothing to buy or mount.; SymbolCreator: codlsc
LBL1 = THT-14-423-10: Thermal Transfer Printable Labels, 0.650" W x 0.200" H - 10,000 per roll; Manufacturer: Brady; SymbolCreator: a0412235; CompType: Label; Green_Lifecycle: Not Set; Green_REACh: Incomplete
Logo2 = Pb-Free: SymbolCreator: a0412235
Logo3 = FCC_disclaimer: SymbolCreator: a0412235
ZZ1 = AssemblyNoteLabel: SymbolCreator: a0412235
ZZ2-ZZ4 = AssemblyNote: SymbolCreator: codlsc

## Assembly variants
001: not fitted C51 C52 C53 C54 FID1 FID2 FID3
